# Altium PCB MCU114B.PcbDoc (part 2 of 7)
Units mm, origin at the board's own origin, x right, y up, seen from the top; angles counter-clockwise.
Board outline 105.51 x 58.76 mm, 8 copper layers (Top Layer, GND 2, Signal Layer 3, Power 4, Power 5, Signal Layer 6, GND 7, Bottom), stack 1.554 mm thick; 444 components, 418 nets, 1811 pads, 981 vias.
Unrouted connection lines stored in the file: 3.
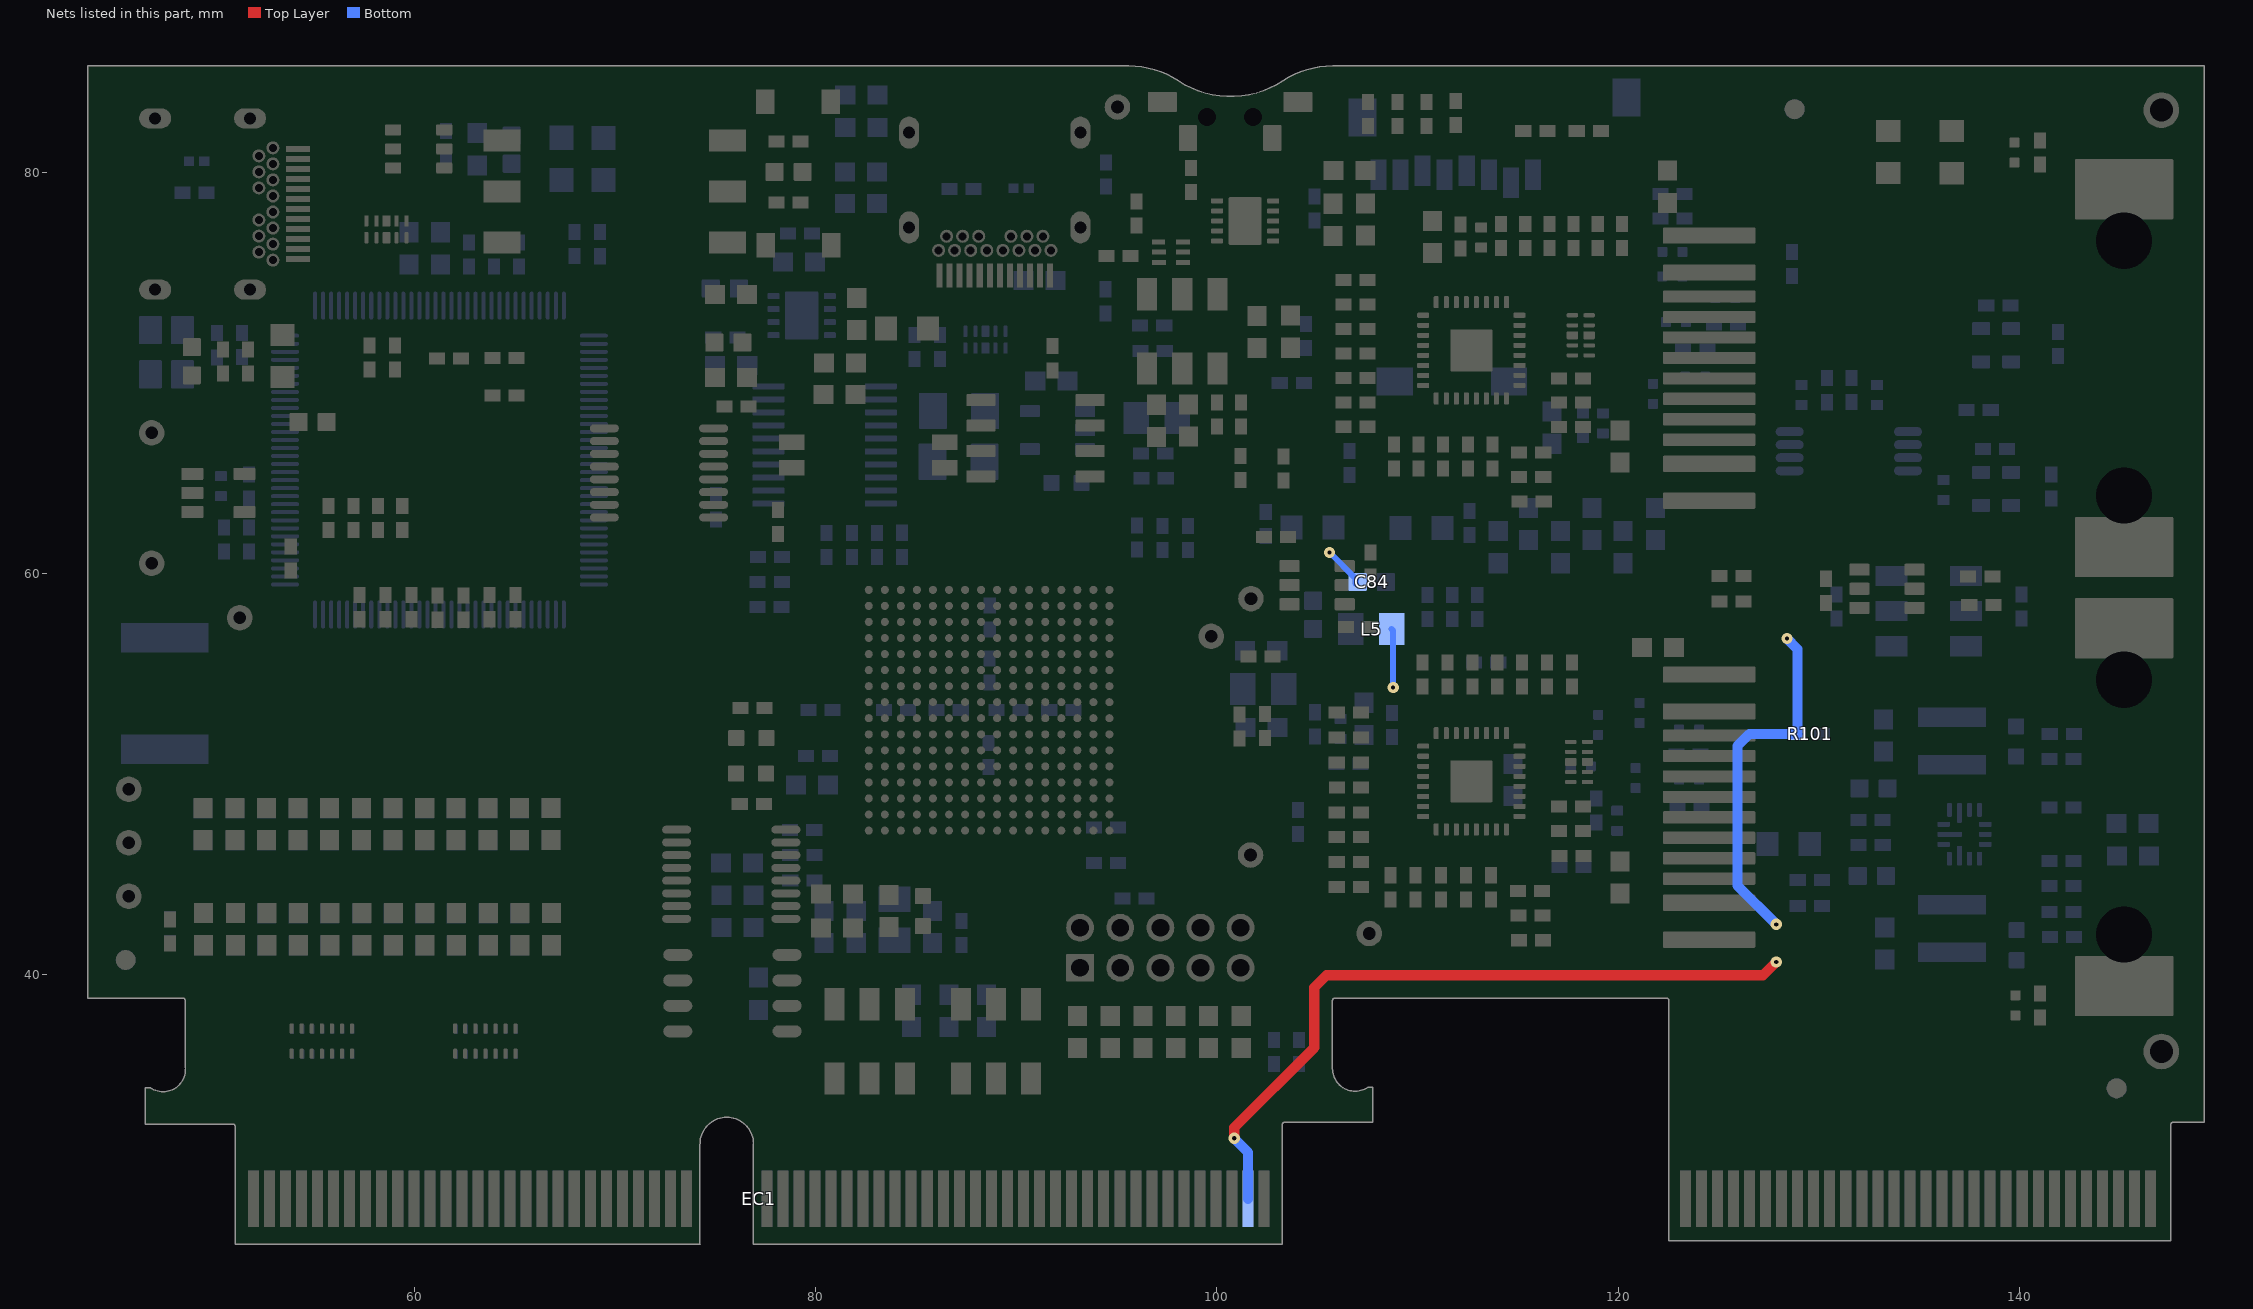
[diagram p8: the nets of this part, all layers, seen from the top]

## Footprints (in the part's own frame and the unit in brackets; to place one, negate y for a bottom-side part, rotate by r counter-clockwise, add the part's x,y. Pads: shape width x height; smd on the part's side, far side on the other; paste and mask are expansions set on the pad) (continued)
D0008A_N [mm] "SOIC, 8-Leads, Body 4.9x3.9mm, Pitch 1.27mm, IPC Medium Density"
  oval 1.45x0.6 smd: 1(-2.725,1.905) 2(-2.725,0.635) 3(-2.725,-0.635) 4(-2.725,-1.905) 5(2.725,-1.905) 6(2.725,-0.635) 7(2.725,0.635) 8(2.725,1.905)
  silkscreen extent -3.3,-2.5 0.9,2.5, body extent -3,-2.45 3,2.45, height 1.63
DBQ0016A_N [mm] "SOP, 16-Leads, Body 4.9x3.9mm, Pitch 0.635mm, IPC Medium Density"
  oval 1.45x0.4 smd: 1(-2.725,2.222) 2(-2.725,1.587) 3(-2.725,0.953) 4(-2.725,0.318) 5(-2.725,-0.318) 6(-2.725,-0.953) 7(-2.725,-1.587) 8(-2.725,-2.222) 9(2.725,-2.222) 10(2.725,-1.587) 11(2.725,-0.953) 12(2.725,-0.318) 13(2.725,0.318) 14(2.725,0.953) 15(2.725,1.587) 16(2.725,2.222)
  silkscreen extent -3.35,-2.5 1.1,2.68, body extent -3.01,-2.45 3.01,2.45, height 1.63
DBV0005A-MFG [mm]
  rrect17% 1.1x0.6 smd paste+0 mask+0: 1(-1.3,0.95) 2(-1.3,0) 3(-1.3,-0.95) 4(1.3,-0.95) 5(1.3,0.95)
  silkscreen extent -2.57,-1.53 0.87,1.53, body extent -1.95,-1.78 1.95,1.78, height 0.25
DBV0005A_N [mm] "SOT23, 5-Leads, Body 2.9x1.6mm, Pitch 0.95mm, Lead Span 2.8mm, IPC Medium Density"
  rrect17% 1x0.6 smd: 1(-1.375,0.95) 2(-1.375,0) 3(-1.375,-0.95) 4(1.375,-0.95) 5(1.375,0.95)
  silkscreen extent -0.25,-1.55 0.25,1.55, body extent -1.42,-1.46 1.42,1.46, height 1.09
DBV0006A_L [mm] "SOT23, 6-Leads, Body 2.9x1.6mm, Pitch 0.95mm, Lead Span 2.8mm, IPC High Density"
  rrect18% 0.8x0.55 smd: 1(-1.275,0.95) 2(-1.275,0) 3(-1.275,-0.95) 4(1.275,-0.95) 5(1.275,0) 6(1.275,0.95)
  silkscreen extent -1.55,-1.53 0.55,1.53, body extent -1.42,-1.46 1.42,1.46, height 1.12
DBV0006A_N [mm] "SOT23, 6-Leads, Body 2.9x1.6mm, Pitch 0.95mm, Lead Span 2.8mm, IPC Medium Density"
  rrect17% 1x0.6 smd: 1(-1.375,0.95) 2(-1.375,0) 3(-1.375,-0.95) 4(1.375,-0.95) 5(1.375,0) 6(1.375,0.95)
  silkscreen extent -1.68,-1.55 0.5,1.55, body extent -1.42,-1.46 1.42,1.46, height 1.12
DLF0004A-MFG [mm]
  rrect15% 0.9x0.65 smd paste-1000 mask+0: 1(-0.75,0.825) 2(-0.75,-0.825) 3(0.75,-0.825) 4(0.75,0.825)
  silkscreen extent -1.88,-0.13 1.05,0.95, body extent -1,-1.25 1,1.25, height 1
DQA0010A#1 [mm] "SON, 10-Leads, Body 1x2.5mm, Pitch 0.5mm, TI Recommended"
  rrect50% 0.565x0.2 smd: 1(-0.417,1) 2(-0.417,0.5) 4(-0.417,-0.5) 5(-0.417,-1) 6(0.417,-1) 7(0.417,-0.5) 9(0.417,0.5) 10(0.417,1)
  rrect28% 0.565x0.36 on Top Paste: 3(-0.417,0) 8(0.417,0)
  rrect25% 0.565x0.4 smd paste-0.2: 3(-0.417,0) 8(0.417,0)
  silkscreen extent -0.67,-1.45 0.55,1.45, body extent -0.55,-1.3 0.55,1.3, height 0.56
DQA0010A#2 [mm] "SON, 10-Leads, Body 1x2.5mm, Pitch 0.5mm, TI Recommended"
  rrect50% 0.565x0.2 smd: 1(-0.417,1) 2(-0.417,0.5) 4(-0.417,-0.5) 5(-0.417,-1) 6(0.417,-1) 7(0.417,-0.5) 9(0.417,0.5) 10(0.417,1)
  rrect28% 0.565x0.36 on Bottom Paste: 3(-0.417,0) 8(0.417,0)
  rrect25% 0.565x0.4 smd paste-0.2: 3(-0.417,0) 8(0.417,0)
  silkscreen extent -0.67,-1.45 0.55,1.45, body extent -0.55,-1.3 0.55,1.3, height 0.56
DRB0008B [mm] "SON, 8-Leads, Body 3x3mm, Pitch 0.65mm, Thermal Pad 2.4x1.65mm, TI Recommended"
  rrect33% 0.6x0.3 smd: 1(-1.4,0.975) 2(-1.4,0.325) 3(-1.4,-0.325) 4(-1.4,-0.975) 5(1.4,-0.975) 6(1.4,-0.325) 7(1.4,0.325) 8(1.4,0.975)
  rrect9% 1.47x1.06 on Bottom Paste: 9(0,-0.63) 9(0,0.63)
  rrect6% 1.65x2.4 smd paste-1.2 mask+0.05: 9(0,0)
  silkscreen extent -1.73,-1.73 1.73,1.73, body extent -1.5,-1.5 1.5,1.5, height 0.96
DRC0010R [mm] "VSON-10"
  rrect40% 0.6x0.25 smd: 1(-1.4,1) 2(-1.4,0.5) 3(-1.4,0) 4(-1.4,-0.5) 5(-1.4,-1) 6(1.4,-1) 7(1.4,-0.5) 8(1.4,0) 9(1.4,0.5) 10(1.4,1)
  rrect12% 1.65x2.4 smd paste-1 mask+0.05: 11(0,0)
  Top Layer region: -0.375,-1.65 -0.375,-1.2 -0.775,-1.2 -0.794,-1.196 -0.81,-1.185 -0.821,-1.169 -0.825,-1.15 -0.825,-1.15 -0.825,1.15 -0.821,1.169 -0.81,1.185 -0.794,1.196 -0.775,1.2 -0.775,1.2 -0.375,1.2 -0.375,1.65 -0.371,1.669 -0.36,1.685 -0.344,1.696 -0.325,1.7 -0.325,1.7 -0.325,1.7 -0.175,1.7 -0.175,1.7 -0.156,1.696 -0.14,1.685 -0.129,1.669 -0.125,1.65 -0.125,1.65 -0.125,1.2 0.125,1.2 0.125,1.65 0.129,1.669 0.14,1.685 0.156,1.696 0.175,1.7 0.175,1.7 0.175,1.7 0.325,1.7 0.325,1.7 0.344,1.696 0.36,1.685 0.371,1.669 0.375,1.65 0.375,1.65 0.375,1.2 0.775,1.2 0.794,1.196 0.81,1.185 0.821,1.169 0.825,1.15 0.825,1.15 0.825,-1.15 0.821,-1.169 0.81,-1.185 0.794,-1.196 0.775,-1.2 0.775,-1.2 0.375,-1.2 0.375,-1.65 0.371,-1.669 0.36,-1.685 0.344,-1.696 0.325,-1.7 0.325,-1.7 0.175,-1.7 0.156,-1.696 0.14,-1.685 0.129,-1.669 0.125,-1.65 0.125,-1.65 0.125,-1.2 -0.125,-1.2 -0.125,-1.65 -0.129,-1.669 -0.14,-1.685 -0.156,-1.696 -0.175,-1.7 -0.175,-1.7 -0.325,-1.7 -0.344,-1.696 -0.36,-1.685 -0.371,-1.669 -0.375,-1.65
  silkscreen extent -1.65,-1.65 1.65,1.65, body extent -1.5,-1.5 1.5,1.5, height 0.87
DSE0006A [mm] "TI recommended land pattern"
  rect 0.66x0.25 smd: 1(-0.62,0.5)
  rect 0.7x0.25 smd: 2(-0.6,0) 3(-0.6,-0.5) 4(0.6,-0.5) 5(0.6,0) 6(0.6,0.5)
  Top Layer region: -0.3,0.625 -0.25,0.625 -0.15,0.525 -0.15,0.375 -0.3,0.375
  silkscreen extent -0.9,-0.92 0.9,0.92, body extent -0.77,-0.77 0.77,0.77, height 0.8
EtherCAT_label [mm] "ETHERCAT_LABEL"
FCC_disclaimer [mm]
Fiducial10-20#1 [mm]
  round 1 smd mask+0.5: 1(0,0)
  Top Layer keep-out circle w1.178: c0,0 r0.5
Fiducial10-20#2 [mm]
  round 1 smd far side mask+0.5: 1(0,0)
  Top Layer keep-out circle w1.178: c0,0 r0.5
FP-830064296_SMT4_3MM4_2MM7-MFG [mm]
  rrect9% 1.4x1.15 smd paste+0 mask+0: 1(-1.1,-0.8) 2(1.1,-0.8) 3(1.1,0.8) 4(-1.1,0.8)
  silkscreen extent -2.17,-2.05 2.17,1.35, body extent -1.7,-1.35 1.7,1.35, height 0.8
FP-885012005053_0402-MFG [mm]
  rrect20% 0.5x0.5 smd paste+0 mask+0: 1(-0.5,0) 2(0.5,0)
  silkscreen extent -0.53,-0.63 0.53,0.63, body extent -0.5,-0.25 0.5,0.25, height 0.55
FP-885012006032_0603-MFG [mm]
  rrect13% 0.8x0.8 smd paste+0 mask+0: 1(-0.75,0) 2(0.75,0)
  silkscreen extent -0.85,-0.77 0.85,0.77, body extent -0.8,-0.4 0.8,0.4, height 0.87
FP-885012106012_0603-MFG [mm]
  rrect13% 0.8x0.8 smd paste+0 mask+0: 1(-0.75,0) 2(0.75,0)
  silkscreen extent -0.85,-0.77 0.85,0.77, body extent -0.8,-0.4 0.8,0.4, height 0.87
FP-885012205067_0402-MFG [mm]
  rrect20% 0.5x0.5 smd paste+0 mask+0: 1(-0.5,0) 2(0.5,0)
  silkscreen extent -0.53,-0.63 0.53,0.63, body extent -0.85,-0.38 0.85,0.38, height 0.25
FP-885012205086_0402-MFG [mm]
  rrect20% 0.5x0.5 smd paste+0 mask+0: 1(-0.5,0) 2(0.5,0)
  silkscreen extent -0.6,-0.63 0.6,0.63, body extent -0.5,-0.25 0.5,0.25, height 0.7
FP-CC0603KRX5R7BB106_0603-MFG [mm]
  rrect11% 0.9x0.9 smd paste+0 mask+0: 1(-0.7,0) 2(0.7,0)
  silkscreen extent -0.9,-0.82 0.9,0.82, body extent -1.35,-0.75 1.35,0.75, height 0.25
FP-CL388-IPC_C [mm]
  rect 0.515x0.472 smd paste+0 mask+0: 1(-0.379,0) 2(0.379,0)
  silkscreen extent -0.64,-0.67 0.64,0.67, body extent -0.5,-0.25 0.5,0.25, height 0.55
"FP-RMCF0402ZT0R00_0402 (1005 metric)-0" [mm]
  rrect20% 0.5x0.6 smd paste+0 mask+0: 1(-0.5,0) 2(0.5,0)
  body extent -0.5,-0.25 0.5,0.25, height 0.35
FP-RT0402FRE0751RL_0402-MFG [mm]
  rrect20% 0.5x0.6 smd paste+0 mask+0: 1(-0.5,0) 2(0.5,0)
  silkscreen extent -0.5,-0.71 0.5,0.7, body extent -0.5,-0.25 0.5,0.25, height 0.35
FP-TMM-105-01-T-D_HDR10-MFG [mm]
  rrect7% 1.39x1.39 hole 0.89 paste-2539.97 mask+0: 1(-4,-1)
  round 1.39 hole 0.89 paste-2539.97 mask+0: 2(-4,1) 3(-2,-1) 4(-2,1) 5(0,-1) 6(0,1) 7(2,-1) 8(2,1) 9(4,-1) 10(4,1)
  body extent -5.1,-2.13 5.1,2.13, height 0.25
LTST-C170TBKT_Blue [mm] "LITE-ON"
  rect 1.2x1.2 smd: 1(-1.05,0) 2(1.05,0)
  silkscreen extent -1.6,-1 2.2,1, body extent -1.05,-0.67 1.05,0.67, height 1.2
PDT0128A [mm] "Thin QFP, 128-Leads, Body 14x14mm, Pitch 0.4mm"
  oval 1.4x0.2 smd: 1(-7.7,6.2) 2(-7.7,5.8) 3(-7.7,5.4) 4(-7.7,5) 5(-7.7,4.6) 6(-7.7,4.2) 7(-7.7,3.8) 8(-7.7,3.4) 9(-7.7,3) 10(-7.7,2.6) 11(-7.7,2.2) 12(-7.7,1.8) 13(-7.7,1.4) 14(-7.7,1) 15(-7.7,0.6) 16(-7.7,0.2) 17(-7.7,-0.2) 18(-7.7,-0.6) 19(-7.7,-1) 20(-7.7,-1.4) 21(-7.7,-1.8) 22(-7.7,-2.2) 23(-7.7,-2.6) 24(-7.7,-3) 25(-7.7,-3.4) 26(-7.7,-3.8) 27(-7.7,-4.2) 28(-7.7,-4.6) 29(-7.7,-5) 30(-7.7,-5.4) 31(-7.7,-5.8) 32(-7.7,-6.2) 65(7.7,-6.2) 66(7.7,-5.8) 67(7.7,-5.4) 68(7.7,-5) 69(7.7,-4.6) 70(7.7,-4.2) 71(7.7,-3.8) 72(7.7,-3.4) 73(7.7,-3) 74(7.7,-2.6) 75(7.7,-2.2) 76(7.7,-1.8) 77(7.7,-1.4) 78(7.7,-1) 79(7.7,-0.6) 80(7.7,-0.2) 81(7.7,0.2) 82(7.7,0.6) 83(7.7,1) 84(7.7,1.4) 85(7.7,1.8) 86(7.7,2.2) 87(7.7,2.6) 88(7.7,3) 89(7.7,3.4) 90(7.7,3.8) 91(7.7,4.2) 92(7.7,4.6) 93(7.7,5) 94(7.7,5.4) 95(7.7,5.8) 96(7.7,6.2)
  oval 0.2x1.4 smd: 33(-6.2,-7.7) 34(-5.8,-7.7) 35(-5.4,-7.7) 36(-5,-7.7) 37(-4.6,-7.7) 38(-4.2,-7.7) 39(-3.8,-7.7) 40(-3.4,-7.7) 41(-3,-7.7) 42(-2.6,-7.7) 43(-2.2,-7.7) 44(-1.8,-7.7) 45(-1.4,-7.7) 46(-1,-7.7) 47(-0.6,-7.7) 48(-0.2,-7.7) 49(0.2,-7.7) 50(0.6,-7.7) 51(1,-7.7) 52(1.4,-7.7) 53(1.8,-7.7) 54(2.2,-7.7) 55(2.6,-7.7) 56(3,-7.7) 57(3.4,-7.7) 58(3.8,-7.7) 59(4.2,-7.7) 60(4.6,-7.7) 61(5,-7.7) 62(5.4,-7.7) 63(5.8,-7.7) 64(6.2,-7.7) 97(6.2,7.7) 98(5.8,7.7) 99(5.4,7.7) 100(5,7.7) 101(4.6,7.7) 102(4.2,7.7) 103(3.8,7.7) 104(3.4,7.7) 105(3,7.7) 106(2.6,7.7) 107(2.2,7.7) 108(1.8,7.7) 109(1.4,7.7) 110(1,7.7) 111(0.6,7.7) 112(0.2,7.7) 113(-0.2,7.7) 114(-0.6,7.7) 115(-1,7.7) 116(-1.4,7.7) 117(-1.8,7.7) 118(-2.2,7.7) 119(-2.6,7.7) 120(-3,7.7) 121(-3.4,7.7) 122(-3.8,7.7) 123(-4.2,7.7) 124(-4.6,7.7) 125(-5,7.7) 126(-5.4,7.7) 127(-5.8,7.7) 128(-6.2,7.7)
  silkscreen extent -7.7,-6.3 6.3,6.99, body extent -8,-8 8,8, height 1.07
PW0008A_N [mm] "TSOP, 8-Leads, Body 3x4.4mm, Pitch 0.65mm, IPC Medium Density"
  oval 1.4x0.45 smd: 1(-2.95,0.975) 2(-2.95,0.325) 3(-2.95,-0.325) 4(-2.95,-0.975) 5(2.95,-0.975) 6(2.95,-0.325) 7(2.95,0.325) 8(2.95,0.975)
  silkscreen extent -3.4,-1.55 1.85,1.55, body extent -3.21,-1.5 3.21,1.5, height 1.2
PW0020A-MFG [mm]
  rrect33% 1.6x0.3 smd paste-1000 mask+0: 1(-2.8,2.925) 2(-2.8,2.275) 3(-2.8,1.625) 4(-2.8,0.975) 5(-2.8,0.325) 6(-2.8,-0.325) 7(-2.8,-0.975) 8(-2.8,-1.625) 9(-2.8,-2.275) 10(-2.8,-2.925) 11(2.8,-2.925) 12(2.8,-2.275) 13(2.8,-1.625) 14(2.8,-0.975) 15(2.8,-0.325) 16(2.8,0.325) 17(2.8,0.975) 18(2.8,1.625) 19(2.8,2.275) 20(2.8,2.925)
  silkscreen extent -4.3,-3.3 1.63,3.3, body extent -3.2,-3.25 3.2,3.25, height 1.2
RHB0032M-MFG [mm]
  rrect40% 0.6x0.25 smd paste+0 mask+0: 1(-2.4,1.75) 2(-2.4,1.25) 3(-2.4,0.75) 4(-2.4,0.25) 5(-2.4,-0.25) 6(-2.4,-0.75) 7(-2.4,-1.25) 8(-2.4,-1.75) 17(2.4,-1.75) 18(2.4,-1.25) 19(2.4,-0.75) 20(2.4,-0.25) 21(2.4,0.25) 22(2.4,0.75) 23(2.4,1.25) 24(2.4,1.75)
  rrect40% 0.25x0.6 smd paste+0 mask+0: 9(-1.75,-2.4) 10(-1.25,-2.4) 11(-0.75,-2.4) 12(-0.25,-2.4) 13(0.25,-2.4) 14(0.75,-2.4) 15(1.25,-2.4) 16(1.75,-2.4) 25(1.75,2.4) 26(1.25,2.4) 27(0.75,2.4) 28(0.25,2.4) 29(-0.25,2.4) 30(-0.75,2.4) 31(-1.25,2.4) 32(-1.75,2.4)
  rrect5% 2.1x2.1 smd paste-1000 mask+0: 33(0,0)
  silkscreen extent -3.4,-2.55 2.55,2.55, body extent -2.8,-2.8 2.8,2.8, height 0.25
RQR0014A-MFG [mm]
  rrect40% 0.625x0.25 smd paste+0 mask+0: 1(-1.038,0.5) 2(-1.038,0) 3(-1.038,-0.5) 8(1.038,-0.5) 10(1.038,0.5)
  rrect40% 0.25x0.675 smd paste+0 mask+0: 4(-0.75,-1.212) 5(-0.25,-1.212) 7(0.75,-1.212) 11(0.75,1.212) 13(-0.25,1.212) 14(-0.75,1.212)
  rrect40% 0.25x0.975 smd paste+0 mask+0: 6(0.25,-1.062) 12(0.25,1.062)
  rrect40% 1.225x0.25 smd paste+0 mask+0: 9(0.737,0)
  silkscreen extent -2.02,-1.55 1.35,1.55, body extent -1.15,-1.35 1.15,1.35, height 1
RVZ0014A [mm] "SON, 14-Leads, Body 3.5x1.35mm, Pitch 0.5mm"
  rrect50% 0.5x0.2 smd: 1(-0.625,1.5) 2(-0.625,1) 3(-0.625,0.5) 4(-0.625,0) 5(-0.625,-0.5) 6(-0.625,-1) 7(-0.625,-1.5) 8(0.625,-1.5) 9(0.625,-1) 10(0.625,-0.5) 11(0.625,0) 12(0.625,0.5) 13(0.625,1) 14(0.625,1.5)
  silkscreen extent -1.18,-2.05 1.18,2.05, body extent -0.72,-1.8 0.72,1.8, height 0.55
SOD-123 [mm] "On Semi recommended land pattern"
  rect 0.915x1.22 smd: 1(-1.637,0) 2(1.637,0)
  silkscreen extent -2.74,-1.17 2.03,1.17, body extent -1.93,-0.9 1.93,0.9, height 1.35
SOIC-8 [mm] "duplicate of SO-8.  SOIC, 8-Leads, Body 5.0x4.0mm (max), Pitch 1.27mm, IPC Medium Density"
  rrect17% 1.45x0.6 smd: 1(-2.725,1.905) 2(-2.725,0.635) 3(-2.725,-0.635) 4(-2.725,-1.905) 5(2.725,-1.905) 6(2.725,-0.635) 7(2.725,0.635) 8(2.725,1.905)
  silkscreen extent -3.5,-2.5 0.9,2.5, body extent -3,-2.45 3,2.45, height 1.63
SW_218-2LP [mm] "SMD, 4-Leads, Body 3.71x5.8mm, Pitch 1.27mm"
  rect 1.27x0.76 smd: 1(-3.81,0.635) 2(-3.81,-0.635) 3(3.81,-0.635) 4(3.81,0.635)
  silkscreen extent -2.9,-1.86 2.9,2.09, body extent -4.22,-1.86 4.22,1.85, height 2.62
SW_1188E [mm] "SMD, 4-Leads, Body 7.8x3.5mm"
  rrect10% 1x1.45 smd: 1(-1.1,3.375) 2(-1.1,-3.375)
  rrect11% 1.3x0.9 smd: 3(0.7,2.1) 4(0.7,-2.1)
  round 0 hole 0.9 unplated: ""(-0.35,1.15) ""(-0.35,-1.15)
  silkscreen extent -1.97,-2.28 0.95,2.28, body extent -2.55,-3.9 1.05,3.9, height 3.5
SW_CAS-D20TA [mm] "SMD, 6-Leads, Body 5.4x3.9mm, Pitch 1.75mm"
  rect 1.6x1 smd: 1(-1.85,1.75) 2(-1.85,0) 3(-1.85,-1.75) 4(1.85,1.75) 5(1.85,0) 6(1.85,-1.75)
  silkscreen extent -1.95,-2.7 1.95,2.9, body extent -2.1,-2.7 2.1,2.7, height 2.5
TI_Stacked_Overlay_Small [mm]
  silkscreen extent -10.63,-2.49 10.63,2.49
TP_50MIL-25MILHOLE [mm]
  round 1.27 hole 0.635: 1(0,0)
WEEE_Minimum [mm] "WEEElie bin"
  silkscreen extent -2.42,-4.38 2.52,2.65
WL-SMCW_Green_0805 [mm] "SMD, 2-Leads, Body 2x1.25mm"
  rect 1.1x1.2 smd: 1(-1.05,0) 2(1.05,0)
  silkscreen extent -2.4,-1.1 1.5,1.1, body extent -1,-0.62 1,0.63, height 0.7
WL-SMCW_RED_0805 [mm] "SMD, 2-Leads, Body 1.6x0.8mm"
  rect 1.1x1.2 smd: 1(-1.05,0) 2(1.05,0)
  silkscreen extent -2.4,-1.1 1.5,1.1, body extent -1,-0.62 1,0.63, height 0.7
Wurth_632_723_300_011 [mm] "Connector, Receptacle, USB Type C, R/A"
  rect 0.3x1.2 smd: A1(-2.75,10.58) A2(-2.25,10.58) A3(-1.75,10.58) A4(-1.25,10.58) A5(-0.75,10.58) A6(-0.25,10.58) A7(0.25,10.58) A8(0.75,10.58) A9(1.25,10.58) A10(1.75,10.58) A11(2.25,10.58) A12(2.75,10.58)
  round 0.65 hole 0.4 mask+0: B1(2.8,9.32) B2(2.4,8.62) B3(1.6,8.62) B4(1.2,9.32) B5(0.8,8.62) B6(0.4,9.32) B7(-0.4,9.32) B8(-0.8,8.62) B9(-1.2,9.32) B10(-1.6,8.62) B11(-2.4,8.62) B12(-2.8,9.32) M1(2,9.32) M2(-2,9.32)
  rrect100% 1x1.6 hole 0.6 slot 1.2 at 90 deg: S1(-4.27,8.18) S2(-4.27,3.45) S3(4.27,3.45) S4(4.27,8.18)
  silkscreen extent -4.37,0.15 4.37,10.36, body extent -4.37,-0.96 4.37,10.83, height 3.07
Wurth_750315371 [mm] "SMD, Body 12.6x8.3mm, Pitch 2.54mm"
  rect 1.83x1.09 smd: 1(-5.62,2.54) 2(-5.62,0) 3(-5.62,-2.54) 4(5.62,-2.54) 5(5.62,0) 6(5.62,2.54)
  silkscreen extent -6.3,-4.15 6.3,4.4, body extent -6.35,-4.2 6.35,4.2, height 4.11
Wurth_7498010210A [mm] "Connector, RJ45, 1x1, Gold, R/A, SMT"
  rrect12% 4.6x0.81 smd: 1(-20.69,6.61) 2(-20.69,4.77) 11(-20.69,-4.77) 12(-20.69,-6.61)
  rrect16% 4.6x0.61 smd: 3(-20.69,3.57) 4(-20.69,2.55) 5(-20.69,1.53) 6(-20.69,0.51) 7(-20.69,-0.51) 8(-20.69,-1.53) 9(-20.69,-2.55) 10(-20.69,-3.57)
  rrect3% 4.9x3 smd: 13(0,8.92) 14(0,-8.92)
  round 2.5 hole 2.8 unplated mask+0.102: ALIGN1(0,6.35) ALIGN2(0,-6.35)
  body extent -21.42,-9.65 5.43,9.65, height 15.22
XFL4015 [mm] "SMD, 2-Leads, Body 4x4mm"
  rect 0.98x3.4 smd: 1(-1.185,0) 2(1.185,0)
  silkscreen extent -2.15,-2.15 2.15,2.15, body extent -2.15,-2.15 2.15,2.15, height 1.6
ZEJ0256A-MFG [mm]
  round 0.4 smd paste+0 mask-1000: A1(-6,6) A2(-5.2,6) A3(-4.4,6) A4(-3.6,6) A5(-2.8,6) A6(-2,6) A7(-1.2,6) A8(-0.4,6) A9(0.4,6) A10(1.2,6) A11(2,6) A12(2.8,6) A13(3.6,6) A14(4.4,6) A15(5.2,6) A16(6,6) B1(-6,5.2) B2(-5.2,5.2) B3(-4.4,5.2) B4(-3.6,5.2) B5(-2.8,5.2) B6(-2,5.2) B7(-1.2,5.2) B8(-0.4,5.2) B9(0.4,5.2) B10(1.2,5.2) B11(2,5.2) B12(2.8,5.2) B13(3.6,5.2) B14(4.4,5.2) B15(5.2,5.2) B16(6,5.2) C1(-6,4.4) C2(-5.2,4.4) C3(-4.4,4.4) C4(-3.6,4.4) C5(-2.8,4.4) C6(-2,4.4) C7(-1.2,4.4) C8(-0.4,4.4) C9(0.4,4.4) C10(1.2,4.4) C11(2,4.4) C12(2.8,4.4) C13(3.6,4.4) C14(4.4,4.4) C15(5.2,4.4) C16(6,4.4) D1(-6,3.6) D2(-5.2,3.6) D3(-4.4,3.6) D4(-3.6,3.6) D5(-2.8,3.6) D6(-2,3.6) D7(-1.2,3.6) D8(-0.4,3.6) D9(0.4,3.6) D10(1.2,3.6) D11(2,3.6) D12(2.8,3.6) D13(3.6,3.6) D14(4.4,3.6) D15(5.2,3.6) D16(6,3.6) E1(-6,2.8) E2(-5.2,2.8) E3(-4.4,2.8) E4(-3.6,2.8) E5(-2.8,2.8) E6(-2,2.8) E7(-1.2,2.8) E8(-0.4,2.8) E9(0.4,2.8) E10(1.2,2.8) E11(2,2.8) E12(2.8,2.8) E13(3.6,2.8) E14(4.4,2.8) E15(5.2,2.8) E16(6,2.8) F1(-6,2) F2(-5.2,2) F3(-4.4,2) F4(-3.6,2) F5(-2.8,2) F6(-2,2) F7(-1.2,2) F8(-0.4,2) F9(0.4,2) F10(1.2,2) F11(2,2) F12(2.8,2) F13(3.6,2) F14(4.4,2) F15(5.2,2) F16(6,2) G1(-6,1.2) G2(-5.2,1.2) G3(-4.4,1.2) G4(-3.6,1.2) G5(-2.8,1.2) G6(-2,1.2) G7(-1.2,1.2) G8(-0.4,1.2) G9(0.4,1.2) G10(1.2,1.2) G11(2,1.2) G12(2.8,1.2) G13(3.6,1.2) G14(4.4,1.2) G15(5.2,1.2) G16(6,1.2) H1(-6,0.4) H2(-5.2,0.4) H3(-4.4,0.4) H4(-3.6,0.4) H5(-2.8,0.4) H6(-2,0.4) H7(-1.2,0.4) H8(-0.4,0.4) H9(0.4,0.4) H10(1.2,0.4) H11(2,0.4) H12(2.8,0.4) H13(3.6,0.4) H14(4.4,0.4) H15(5.2,0.4) H16(6,0.4) J1(-6,-0.4) J2(-5.2,-0.4) J3(-4.4,-0.4) J4(-3.6,-0.4) J5(-2.8,-0.4) J6(-2,-0.4) J7(-1.2,-0.4) J8(-0.4,-0.4) J9(0.4,-0.4) J10(1.2,-0.4) J11(2,-0.4) J12(2.8,-0.4) J13(3.6,-0.4) J14(4.4,-0.4) J15(5.2,-0.4) J16(6,-0.4) K1(-6,-1.2) K2(-5.2,-1.2) K3(-4.4,-1.2) K4(-3.6,-1.2) K5(-2.8,-1.2) K6(-2,-1.2) K7(-1.2,-1.2) K8(-0.4,-1.2) K9(0.4,-1.2) K10(1.2,-1.2) K11(2,-1.2) K12(2.8,-1.2) K13(3.6,-1.2) K14(4.4,-1.2) K15(5.2,-1.2) K16(6,-1.2) L1(-6,-2) L2(-5.2,-2) L3(-4.4,-2) L4(-3.6,-2) L5(-2.8,-2) L6(-2,-2) L7(-1.2,-2) L8(-0.4,-2) L9(0.4,-2) L10(1.2,-2) L11(2,-2) L12(2.8,-2) L13(3.6,-2) L14(4.4,-2) L15(5.2,-2) L16(6,-2) M1(-6,-2.8) M2(-5.2,-2.8) M3(-4.4,-2.8) M4(-3.6,-2.8) M5(-2.8,-2.8) M6(-2,-2.8) M7(-1.2,-2.8) M8(-0.4,-2.8) M9(0.4,-2.8) M10(1.2,-2.8) M11(2,-2.8) M12(2.8,-2.8) M13(3.6,-2.8) M14(4.4,-2.8) M15(5.2,-2.8) M16(6,-2.8) N1(-6,-3.6) N2(-5.2,-3.6) N3(-4.4,-3.6) N4(-3.6,-3.6) N5(-2.8,-3.6) N6(-2,-3.6) N7(-1.2,-3.6) N8(-0.4,-3.6) N9(0.4,-3.6) N10(1.2,-3.6) N11(2,-3.6) N12(2.8,-3.6) N13(3.6,-3.6) N14(4.4,-3.6) N15(5.2,-3.6) N16(6,-3.6) P1(-6,-4.4) P2(-5.2,-4.4) P3(-4.4,-4.4) P4(-3.6,-4.4) P5(-2.8,-4.4) P6(-2,-4.4) P7(-1.2,-4.4) P8(-0.4,-4.4) P9(0.4,-4.4) P10(1.2,-4.4) P11(2,-4.4) P12(2.8,-4.4) P13(3.6,-4.4) P14(4.4,-4.4) P15(5.2,-4.4) P16(6,-4.4) R1(-6,-5.2) R2(-5.2,-5.2) R3(-4.4,-5.2) R4(-3.6,-5.2) R5(-2.8,-5.2) R6(-2,-5.2) R7(-1.2,-5.2) R8(-0.4,-5.2) R9(0.4,-5.2) R10(1.2,-5.2) R11(2,-5.2) R12(2.8,-5.2) R13(3.6,-5.2) R14(4.4,-5.2) R15(5.2,-5.2) R16(6,-5.2) T1(-6,-6) T2(-5.2,-6) T3(-4.4,-6) T4(-3.6,-6) T5(-2.8,-6) T6(-2,-6) T7(-1.2,-6) T8(-0.4,-6) T9(0.4,-6) T10(1.2,-6) T11(2,-6) T12(2.8,-6) T13(3.6,-6) T14(4.4,-6) T15(5.2,-6) T16(6,-6)
  silkscreen extent -7.25,-6.65 6.65,6.65, body extent -7.05,-7.05 7.05,7.05, height 0.25

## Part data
B1: library part CMP-0860874-2, "3.3-V and 2.5-V LVCMOS High-Performance Clock Buffer Family, PW0008A (TSSOP-8)", Alternate Manufacturer="Texas Instruments", Alternate PartNumber=LMK1C1104PWR
C1 C2 C3 C4 C9 C19: library part CMP-0006227-2, "CAP, CERM, 0.01 uF, 16 V, +/- 10%, X7R, 0402", Cap_Case=0402, Manufacturer="Wurth Elektronik", Supplier Part Number 1=710-885012205031, TempCo=X7R, Tolerance_%=10%, Value1=Unknown, Value2=16V, ValueDisplayed=0.01uF
C5 C6 C11 C15 C16 C22 C23 C25 C27 C29 C30 C31 C35 C36 C37 C38 C39 C40 C41 C42 C43 C51 C52 C55 C56 C57 C58 C59 C60 C61 C68 C69 C70 C71 C72 C73 C74 C75 C76 C77 C78 C79 C80 C81 C82 C83 C86 C90 C98 C100 C103 C106 C114 C116 C126 C152 C153: library part CMP-0006228-2, "CAP, CERM, 0.1 uF, 16 V, +/- 10%, X7R, 0402", Cap_Case=0402, Manufacturer="Wurth Elektronik", Supplier Part Number 1=732-7532-1-ND, TempCo=X7R, Tolerance_%=10%, Value1=Unknown, Value2=16V, ValueDisplayed=0.1uF
C7 C8 C12: library part CMP-0064924-2, "CAP, CERM, 1 uF, 10 V,+/- 20%, X5R, 0402", Cap_Case=0402, Manufacturer="Wurth Elektronik", Supplier Part Number 1=732-7489-1-ND, TempCo=X5R, Tolerance_%=20%, Value1=Unknown, Value2=10V, ValueDisplayed=1uF
C10: library part CMP-0006222-2, "CAP, CERM, 2.2 uF, 10 V, +/- 20%, X5R, 0402", Cap_Case=0402, Manufacturer="Wurth Elektronik", Supplier Part Number 1=710-885012105013, TempCo=X5R, Tolerance_%=20%, Value1=Unknown, Value2=10V, ValueDisplayed=2.2uF
C13 C14: library part CMP-0006345-2, "CAP, CERM, 12 pF, 50 V, +/- 5%, C0G/NP0, 0402", Cap_Case=0402, Manufacturer="Samsung Electro-Mechanics", Supplier Part Number 1=1276-1178-1-ND, TempCo=C0G/NP0, Tolerance_%=5%, Value1=Unknown, Value2=50V, ValueDisplayed=12pF
C17 C18 C21 C24 C26 C28 C53 C54 C84 C85: library part CMP-0001560-1, "Multilayer Ceramic Capacitors 10uF 16V X5R 10% SMD 0603 85°C Paper T/R - Tape an", Digikey Part Number=311-3486-1-ND, Manufacturer=Yageo, Mouser Part Number=603-CC0603KRX57BB106, Operating Temperature Range="-55°C to +85°C", TempCo=15%, Temperature Characteristic=X5R, Tolerance_%=10%, ValueDisplayed=10uF
C20 C44: library part CMP-13271-000627-1, "Cap Ceramic 3.3nF 50V X7R ±10% SMD 0402 +125°C Paper T/R", Capacitance=3.3nF, Case Code (Imperial)=0402, Case Code (Metric)=1005, Dielectric=X7R, Max Operating Temperature=125°C, Min Operating Temperature=-55°C, Package Quantity=1, Tolerance=10%, Voltage=50V
C32 C33 C64 C65 C66 C67 C120: library part CMP-0006825-5, "CAP, CERM, 2.2 uF, 16 V, +/- 20%, X5R, 0603", Cap_Case=0603, Manufacturer="Wurth Elektronik", Supplier Part Number 1=732-7915-1-ND, TempCo=X5R, Tolerance_%=20%, Value1=Unknown, Value2=16V, ValueDisplayed=2.2uF
C34: library part CMP-0082066-1, "CAP, CERM, 10 pF, 3000 V,+/- 5%, C0G/NP0, AEC-Q200 Grade 1, 1812", Cap_Case=1812, Manufacturer=Kemet, Supplier Part Number 1=399-7113-1-ND, TempCo=C0G/NP0, Tolerance_%=5%, Value2=3000V, ValueDisplayed=10pF
C45 C63 C118 C119: library part CMP-0097305-1, "4.7 µF ±20% 10V Ceramic Capacitor X5R 0603 (1608 Metric)", Digikey Part Number=732-7909-1-ND, Manufacturer="Wurth Electronics", Mouser Part Number=710-885012106012, Operating Temperature Range="-55°C to +85°C", TempCo=15%, Temperature Characteristic=X5R, Tolerance_%=20%, ValueDisplayed=4.7uF
C46: library part CMP-0011440-2, "CAP, TA, 0.1 uF, 35 V, +/- 10%, 20 ohm, SMD", Cap_Case=A, Manufacturer=Vishay-Sprague, Supplier Part Number 1=718-1109-1-ND, Tolerance_%=10%, Value1="20 ohm", Value2=35V, ValueDisplayed=0.1uF
C47: library part CMP-0081926-1, "CAP, TA, 68 µF, 10 V, +/- 20%, 1.5 ohm, SMD", Cap_Case=3216-18, Manufacturer=AVX, Supplier Part Number 1=478-4925-1-ND, Tolerance_%=20%, Value1="1.5 ohm", Value2=10V, ValueDisplayed=68µF
C48 C50: library part CMP-0096972-1, "10 pF ±5% 25V Ceramic Capacitor C0G, NP0 0603 (1608 Metric)", Digikey Part Number=732-7774-1-ND, Manufacturer="Wurth Electronics", Mouser Part Number=710-885012006032, Operating Temperature Range="-55°C to +125°C", TempCo=30ppm/°C, Temperature Characteristic=NP0, Tolerance_%=5%, ValueDisplayed=10pF
C49 C97 C113 C125: library part CMP-0007324-5, "CAP, CERM, 22 uF, 10 V, +/- 20%, X5R, 0603", Cap_Case=0603, Manufacturer=MuRata, Supplier Part Number 1=490-10476-1-ND, TempCo=X5R, Tolerance_%=20%, Value1=Unknown, Value2=10V, ValueDisplayed=22uF
C62 C124: library part CMP-0006829-4, "CAP, CERM, 0.1 uF, 16 V, +/- 10%, X7R, 0603", Cap_Case=0603, Manufacturer="Wurth Elektronik", Supplier Part Number 1=710-885012206046, TempCo=X7R, Tolerance_%=10%, Value1=Unknown, Value2=16V, ValueDisplayed=0.1uF
C87 C95 C102 C111: library part CMP-0096737-1, "100 nF ±10% 50V Ceramic Capacitor X7R 0402 (1005 Metric)", Manufacturer=Wurth, Operating Temperature Range="-55°C to +125°C", TempCo=15%, Temperature Characteristic=X7R, Tolerance_%=10%, ValueDisplayed=100nF
C88 C96 C104 C112: library part CMP-0086061-1, "CAP, CERM, 1 µF, 25 V,+/- 10%, X5R, 0402", Cap_Case=0402, Manufacturer=MuRata, TempCo=X5R, Tolerance_%=10%, Value2=25V, ValueDisplayed=1µF
C89 C105: library part CMP-0006283-2, "CAP, CERM, 2.2 uF, 35 V, +/- 10%, X5R, 0402", Cap_Case=0402_065, Manufacturer=TDK, Supplier Part Number 1=445-9028-1-ND, TempCo=X5R, Tolerance_%=10%, Value1="0.005925 ohm", Value2=35V, ValueDisplayed=2.2uF
C91 C92 C93 C94 C107 C108 C109 C110: library part CMP-0096999-1, "4.7 pF ±0.5pF 50V Ceramic Capacitor C0G, NP0 0402 (1005 Metric)", Digikey Part Number=732-7467-1-ND, Manufacturer="Wurth Electronics", Mouser Part Number=710-885012005053, Operating Temperature Range="-55°C to +125°C", TempCo=30ppm/°C, Temperature Characteristic=NP0, ValueDisplayed=4.7pF
C99 C115: library part CMP-0007313-5, "CAP, CERM, 47 uF, 6.3 V, +/- 20%, X5R, 0603", Cap_Case=0603, Manufacturer=MuRata, TempCo=X5R, Tolerance_%=20%, Value1=Unknown, Value2=6.3V, ValueDisplayed=47uF
C101 C117: library part CMP-0090364-1, "10000pF ±10% 50V Ceramic Capacitor X7R 0402 (1005 Metric)", Digikey Part Number=732-7562-1-ND, Manufacturer="Wurth Electronics", Mouser Part Number=710-885012205067, Operating Temperature Range="-55°C to +125°C", TempCo=15%, Temperature Characteristic=X7R, Tolerance_%=10%, ValueDisplayed=10000pF
C121 C122 C123: library part CMP-0006831-4, "CAP, CERM, 1 uF, 16 V, +/- 10%, X7R, 0603", Cap_Case=0603, Manufacturer="Wurth Elektronik", Supplier Part Number 1=710-885012206052, TempCo=X7R, Tolerance_%=10%, Value1=Unknown, Value2=16V, ValueDisplayed=1uF
C128 C129 C130 C131 C132 C133 C134 C135 C136 C137 C138 C139 C140 C141 C142 C143 C144 C145 C146 C147 C148 C149 C150 C151: library part CMP-0006920-4, "CAP, CERM, 330 pF, 50 V, +/- 5%, C0G/NP0, 0603", Cap_Case=0603, Manufacturer=Kemet, Supplier Part Number 1=399-1068-1-ND, TempCo=C0G/NP0, Tolerance_%=5%, Value1=Unknown, Value2=50V, ValueDisplayed=330pF
D1 D7 D9: library part CMP-0002960-2, "LED, Bright Green, SMD", Color="Bright Green", Manufacturer="Wurth Elektronik", Power_TotalModule=72mW, Supplier Part Number 1=732-4986-1-ND, Value1=0.072W, Value2=2V
D1:A D2:A: library part CMP-0028360-2, "Diode, Schottky, 40 V, 1 A, SOD-123", Manufacturer="Diodes Inc.", Value1=1A, Value2=0.45V
D2 D3 D4 D8: library part CMP-0002951-3, "LED, Red, SMD", Color=Red, Manufacturer="Wurth Elektronik", Power_TotalModule=72mW, Value1=0.072W, Value2=1.9V
D5 D6: library part CMP-0002889-2, "LED, Blue, SMD", Color=Blue, Manufacturer=Lite-On, Value1=W, Value2=3.3V
EC1: library part CMP-0003813-3, "C2000 controlCARD-120HSEC Edge Connector for Samtec HSEC8-160-01-L-DV-A-BL", Manufacturer=Any
EC2: library part CMP-0081961-1, "C2000 controlCARD-180HSEC (60-pin addon) Edge connector for Samtec HSEC8-130-01-L-DV-A", Manufacturer=Any
FID1 FID2 FID3 FID4 FID5 FID6: library part CMP-0077181-1, "Fiducial mark.  There is nothing to buy or mount.", Manufacturer=N/A
J1 J4: library part CMP-0080891-1, "Connector, Receptacle, USB Type C, R/A", Color=Black, Current_A=3A, Manufacturer="Wurth Elektronik", Supplier Part Number 1=732-9618-1-ND, Voltage_V=5V
J2: library part CMP-0075148-2, "Connector, Micro SD, R/A, SMD", Manufacturer=3M, Supplier Part Number 1=3M5607CT-ND
J3: library part CMP-0086568-1, "Board-To-Board Connector, TMM Series, 10 Contacts, Header, 2 mm, Through Hole, 2 Rows", Current_A=3.2A, Manufacturer=Samtec, Voltage_V=281V
J5 J6: library part CMP-0086350-1, "Connector, RJ45, 1x1, Gold, R/A, SMT", Manufacturer="Wurth Elektronik"
L1 L2: library part CMP-0061147-1, "Inductor, Shielded, Composite, 470 nH, 3.5 A, 0.0076 ohm, SMD", Manufacturer=Coilcraft, Supplier Part Number 1=994-XFL4015-471MEC, Value1="0.0076 ohm", Value2=3.5A, ValueDisplayed=470nH
L3 L4: library part CMP-0003093-1, "Ferrite Bead, 60 ohm @ 100 MHz, 3 A, 0805", Manufacturer="Wurth Elektronik", PartNumber=742792063, Supplier Part Number 1=732-1612-1-ND, Value1="0.025 ohm", Value2=3A
L5: library part CMP-0003073-1, "Ferrite Bead, 220 ohm @ 100 MHz, 2 A, 0805", Manufacturer="Wurth Elektronik", PartNumber=742792022, Supplier Part Number 1=732-1614-1-ND, Value1="0.05 ohm", Value2=2A
Logo1: library part CMP-0074844-1
Logo2: library part CMP-0074838-1, "Texas Instrument Corporate Signature"
Logo3: library part CMP-0074847-1, "FCC_disclaimer"
Logo4: library part CMP-0074769-3, Manufacturer="Texas Instruments"
Logo5: library part CMP-0084011-3, "EtherCAT logo"
R1 R10 R11 R31 R36 R37 R38 R43 R51 R54 R72 R100 R103: library part CMP-0077731-1, "RES, 10.0 k, 1%, 0.063 W, AEC-Q200 Grade 0, 0402", Manufacturer="Yageo America", Power_W=63mW, Supplier Part Number 1=YAG3436CT-ND, TempCo="100 ppm/C", Tolerance_%=1%, Value2=0.063W, Value_Code=10k0, ValueDisplayed=10.0k
R2 R46 R58 R73 R80 R81 R82 R83 R84 R86 R87 R91 R92 R93 R97 R99 R101 R110 R144 R203: library part CMP-0026992-3, "RES, 0, 5%, 0.1 W, AEC-Q200 Grade 0, 0402", Manufacturer=Panasonic, Power_W=100mW, Supplier Part Number 1=P0.0JCT-ND, TempCo="600 ppm/C", Tolerance_%=5%, Value2=0.1W, Value_Code=0000, ValueDisplayed=0
R3 R4 R5 R6: library part CMP-0026852-3, "RES, 1.0 k, 5%, 0.063 W, AEC-Q200 Grade 0, 0402", Manufacturer=Vishay-Dale, Power_W=63mW, Supplier Part Number 1=541-1.0KJCT-ND, TempCo="200 ppm/C", Tolerance_%=5%, Value2=0.063W, Value_Code=1k00, ValueDisplayed=1.0k
R7: library part CMP-0026824-3, "RES, 100, 5%, 0.063 W, AEC-Q200 Grade 0, 0402", Manufacturer=Vishay-Dale, Power_W=63mW, Supplier Part Number 1=541-100JCT-ND, TempCo="200 ppm/C", Tolerance_%=5%, Value2=0.063W, Value_Code=100R, ValueDisplayed=100
R8 R9: library part CMP-0026699-1, "RES, 470, 1%, 0.1 W, AEC-Q200 Grade 0, 0402", Manufacturer=Panasonic, Power_W=100mW, Supplier Part Number 1=P470LCT-ND, TempCo="100 ppm/C", Tolerance_%=1%, Value2=0.1W, Value_Code=470R, ValueDisplayed=470
R12: library part CMP-0026413-2, "RES, 4.87 k, 1%, 0.063 W, AEC-Q200 Grade 0, 0402", Manufacturer=Vishay-Dale, Power_W=63mW, Supplier Part Number 1=541-4.87KLCT-ND, TempCo="100 ppm/C", Tolerance_%=1%, Value2=0.063W, Value_Code=4k87, ValueDisplayed=4.87k
R13: library part CMP-0092664-1, "51 Ohms ±1% 0.063W, 1/16W Chip Resistor 0402 (1005 Metric) - Thin Film", Digikey Part Number=13-RT0402FRE0751RLCT-ND, Manufacturer=Yageo, Mouser Part Number=603-RT0402FRE0751RL, Operating Temperature Range="-55°C to +155°C", Part Number=RT0402FRE0751RL, Power_W=63mW, TempCo=50ppm/°C, Tolerance_%=1%
R14 R34 R35 R94 R138: library part CMP-0026962-3, "RES, 680, 5%, 0.063 W, AEC-Q200 Grade 0, 0402", Manufacturer=Vishay-Dale, Power_W=63mW, Supplier Part Number 1=541-680JCT-ND, TempCo="200 ppm/C", Tolerance_%=5%, Value2=0.063W, Value_Code=680R, ValueDisplayed=680
R15 R77 R136 R170: library part CMP-0026757-1, "RES, 1.00 M, 1%, 0.063 W, AEC-Q200 Grade 0, 0402", Manufacturer="Stackpole Electronics Inc", Power_W=63mW, Supplier Part Number 1=RMCF0402FT1M00CT-ND, TempCo="100 ppm/C", Tolerance_%=1%, Value2=0.063W, Value_Code=1M00, ValueDisplayed=1.00M
R16 R17 R79: library part CMP-0025932-5, "RES, 5.1 k, 5%, 0.1 W, 0603", Manufacturer=Yageo, Power_W=100mW, Supplier Part Number 1=311-5.1KGRCT-ND, TempCo="100 ppm/C", Tolerance_%=5%, Value2=0.1W, Value_Code=5k10, ValueDisplayed=5.1k
R18 R20 R27 R28 R29 R33 R44 R45 R47 R49 R50 R52 R55 R56 R59 R60 R64 R66 R70 R75 R78 R96 R98 R172 R173 R174 R175 R176 R177 R178 R179 R180 R181 R182 R183 R184 R185 R186 R187 R188 R189 R190 R191 R192 R193 R194 R195 R196 R197 R198 R212: library part CMP-0025874-4, "RES, 0, 5%, 0.1 W, AEC-Q200 Grade 0, 0603", Manufacturer=Panasonic, Power_W=100mW, Supplier Part Number 1=P0.0GCT-ND, TempCo="600 ppm/C", Tolerance_%=5%, Value2=0.1W, Value_Code=0000, ValueDisplayed=0
R19: library part CMP-0025769-4, "RES, 2.2 k, 5%, 0.1 W, AEC-Q200 Grade 0, 0603", Manufacturer=Vishay-Dale, Power_W=100mW, Supplier Part Number 1=541-2.2KGCT-ND, TempCo="200 ppm/C", Tolerance_%=5%, Value2=0.1W, Value_Code=2k20, ValueDisplayed=2.2k
R21 R57: library part CMP-0022895-5, "RES, 1.00 k, 1%, 0.1 W, 0603", Manufacturer=Yageo, Power_W=100mW, Supplier Part Number 1=311-1.00KHRCT-ND, TempCo="100 ppm/C", Tolerance_%=1%, Value2=0.1W, Value_Code=1k00, ValueDisplayed=1.00k
R22 R23: library part CMP-0025701-4, "RES, 10 k, 5%, 0.1 W, AEC-Q200 Grade 0, 0603", Manufacturer=Vishay-Dale, Power_W=100mW, Supplier Part Number 1=541-10KGCT-ND, TempCo="200 ppm/C", Tolerance_%=5%, Value2=0.1W, Value_Code=10k0, ValueDisplayed=10k
R24: library part CMP-0025927-5, "RES, 4.7 k, 5%, 0.1 W, 0603", Manufacturer=Yageo, Power_W=100mW, Supplier Part Number 1=311-4.7KGRCT-ND, TempCo="100 ppm/C", Tolerance_%=5%, Value2=0.1W, Value_Code=4k70, ValueDisplayed=4.7k
R25: library part CMP-0023109-5, "RES, 430, 1%, 0.1 W, 0603", Manufacturer=Yageo, Power_W=100mW, Supplier Part Number 1=311-430HRCT-ND, TempCo="100 ppm/C", Tolerance_%=1%, Value2=0.1W, Value_Code=430R, ValueDisplayed=430
R26: library part CMP-0025894-5, "RES, 1.2 k, 5%, 0.1 W, 0603", Manufacturer=Yageo, Power_W=100mW, Supplier Part Number 1=311-1.2KGRCT-ND, TempCo="100 ppm/C", Tolerance_%=5%, Value2=0.1W, Value_Code=1k20, ValueDisplayed=1.2k
R30: library part CMP-0026586-2, "RES, 88.7 k, 1%, 0.063 W, AEC-Q200 Grade 0, 0402", Manufacturer=Vishay-Dale, Power_W=63mW, Supplier Part Number 1=541-88.7KLCT-ND, TempCo="100 ppm/C", Tolerance_%=1%, Value2=0.063W, Value_Code=88k7, ValueDisplayed=88.7k
R32 R105 R106 R108 R141 R142 R204 R205: library part CMP-0026631-1, "RES, 4.70 k, 1%, 0.063 W, 0402", Manufacturer="TE Connectivity", Power_W=63mW, Supplier Part Number 1=A121542CT-ND, TempCo="100 ppm/C", Tolerance_%=1%, Value2=0.063W, Value_Code=4k70, ValueDisplayed=4.70k
R39 R40 R139 R140: library part CMP-0026863-2, "RES, 1.5 M, 5%, 0.063 W, AEC-Q200 Grade 0, 0402", Manufacturer=Vishay-Dale, Power_W=63mW, Supplier Part Number 1=541-1.5MJCT-ND, TempCo="200 ppm/C", Tolerance_%=5%, Value2=0.063W, Value_Code=1M50, ValueDisplayed=1.5M
R41: library part CMP-0026815-1, "RES, 100 k, 0.1%, 0.063 W, 0402", Manufacturer="Susumu Co Ltd", Power_W=63mW, Supplier Part Number 1=RG10P100KBCT-ND, TempCo="25 ppm/C", Tolerance_%=0.1%, Value2=0.063W, Value_Code=100k
R42 R61: library part CMP-0026918-5, "RES, 3.3 k, 5%, 0.063 W, AEC-Q200 Grade 0, 0402", Manufacturer=Vishay-Dale, Power_W=63mW, Supplier Part Number 1=541-3.3KJCT-ND, TempCo="200 ppm/C", Tolerance_%=5%, Value2=0.063W, Value_Code=3k30, ValueDisplayed=3.3k
R48 R69 R71 R74 R76: library part CMP-0081856-1, "RES, 0, 0%, 0.2 W, AEC-Q200 Grade 0, 0402", Manufacturer=Vishay-Dale, Power_W=200mW, Supplier Part Number 1=541-0.0YBTR-ND, Tolerance_%=0%, Value2=0.2W, Value_Code=0
R53 R90 R104: library part CMP-0025698-4, "RES, 100 k, 5%, 0.1 W, AEC-Q200 Grade 0, 0603", Manufacturer=Vishay-Dale, Power_W=100mW, Supplier Part Number 1=541-100KGCT-ND, TempCo="200 ppm/C", Tolerance_%=5%, Value2=0.1W, Value_Code=100k
R62 R63: library part CMP-0026949-3, "RES, 56 k, 5%, 0.063 W, AEC-Q200 Grade 0, 0402", Manufacturer=Vishay-Dale, Power_W=63mW, Supplier Part Number 1=541-56KJCT-ND, TempCo="200 ppm/C", Tolerance_%=5%, Value2=0.063W, Value_Code=56k0, ValueDisplayed=56k
R65 R67 R68: library part CMP-0026765-1, "RES, 10.0, 0.1%, 0.063 W, 0402", Manufacturer="TE Connectivity", Power_W=63mW, Supplier Part Number 1=A102583CT-ND, TempCo="25 ppm/C", Tolerance_%=0.1%, Value2=0.063W, Value_Code=10R0, ValueDisplayed=10.0
R85: library part CMP-0020620-3, "RES, 10 k, 5%, 0.125 W, AEC-Q200 Grade 0, 0805", Manufacturer=Panasonic, Power_W=125mW, Supplier Part Number 1=P10KACT-ND, TempCo="200 ppm/C", Tolerance_%=5%, Value2=0.125W, Value_Code=10k0, ValueDisplayed=10k
R88 R89 R111 R112 R113 R127 R128 R129 R130 R133 R145 R146 R147 R161 R162 R163: library part CMP-0026237-2, "RES, 2.49 k, 1%, 0.063 W, AEC-Q200 Grade 0, 0402", Manufacturer=Vishay-Dale, Power_W=63mW, Supplier Part Number 1=541-2.49KLCT-ND, TempCo="100 ppm/C", Tolerance_%=1%, Value2=0.063W, Value_Code=2k49, ValueDisplayed=2.49k
R95: library part CMP-0026068-3, "RES, 19.6 k, 1%, 0.063 W, AEC-Q200 Grade 0, 0402", Manufacturer=Vishay-Dale, Power_W=63mW, Supplier Part Number 1=541-19.6KLCT-ND, TempCo="100 ppm/C", Tolerance_%=1%, Value2=0.063W, Value_Code=19k6, ValueDisplayed=19.6k
R102 R206: library part CMP-0026963-3, "RES, 68 k, 5%, 0.063 W, AEC-Q200 Grade 0, 0402", Manufacturer=Vishay-Dale, Power_W=63mW, Supplier Part Number 1=541-68KJCT-ND, TempCo="200 ppm/C", Tolerance_%=5%, Value2=0.063W, Value_Code=68k0, ValueDisplayed=68k
R107 R123 R124 R125 R151 R159 R160 R202: library part CMP-0026231-2, "RES, 2.20 k, 1%, 0.063 W, AEC-Q200 Grade 0, 0402", Manufacturer=Vishay-Dale, Power_W=63mW, Supplier Part Number 1=541-2.20KLCT-ND, TempCo="100 ppm/C", Tolerance_%=1%, Value2=0.063W, Value_Code=2k20, ValueDisplayed=2.20k
R109 R143: library part CMP-0026515-2, "RES, 6.49 k, 1%, 0.063 W, AEC-Q200 Grade 0, 0402", Manufacturer=Vishay-Dale, Power_W=63mW, Supplier Part Number 1=541-6.49KLCT-ND, TempCo="100 ppm/C", Tolerance_%=1%, Value2=0.063W, Value_Code=6k49, ValueDisplayed=6.49k
R114 R115 R116 R117 R118 R119 R120 R121 R122 R126 R148 R149 R150 R152 R153 R154 R155 R156 R157 R158: library part CMP-0026299-2, "RES, 33.2, 1%, 0.063 W, AEC-Q200 Grade 0, 0402", Manufacturer=Vishay-Dale, Power_W=63mW, Supplier Part Number 1=541-33.2LCT-ND, TempCo="100 ppm/C", Tolerance_%=1%, Value2=0.063W, Value_Code=33R2, ValueDisplayed=33.2
R131 R134 R166 R168: library part CMP-0086542-2, "RMCF/RMCP Series General Purpose Thick Film Standard Power and High Power Chip Resistor", Manufacturer=Stackpole, TempCo=-
R132 R135 R167 R169: library part CMP-0025813-4, "RES, 470, 5%, 0.1 W, AEC-Q200 Grade 0, 0603", Manufacturer=Vishay-Dale, Power_W=100mW, Supplier Part Number 1=541-470GCT-ND, TempCo="200 ppm/C", Tolerance_%=5%, Value2=0.1W, Value_Code=470R, ValueDisplayed=470
R137: library part CMP-0026081-3, "RES, 1.27 k, 1%, 0.063 W, AEC-Q200 Grade 0, 0402", Manufacturer=Vishay-Dale, Power_W=63mW, Supplier Part Number 1=541-1.27KLCT-ND, TempCo="100 ppm/C", Tolerance_%=1%, Value2=0.063W, Value_Code=1k27, ValueDisplayed=1.27k
R171: library part CMP-0026027-3, "RES, 15.0 k, 1%, 0.063 W, AEC-Q200 Grade 0, 0402", Manufacturer=Vishay-Dale, Power_W=63mW, Supplier Part Number 1=541-15.0KLCT-ND, TempCo="100 ppm/C", Tolerance_%=1%, Value2=0.063W, Value_Code=15k0, ValueDisplayed=15.0k
R199 R200 R201: library part CMP-0078660-1, "RES, 0.1, 1%, 0.25 W, 0402", Manufacturer=Panasonic, Power_W=250mW, Supplier Part Number 1=P17368CT-ND, TempCo="300 ppm/C", Tolerance_%=1%, Value2=0.25W, Value_Code=R100, ValueDisplayed=0.1
S1: library part CMP-0002230-1, "Switch, SPST, 2 Pos, 25mA, 24VDC, SMD", CurrentRating_mA=25A, Manufacturer="CTS Electrocomponents", Supplier Part Number 1=CT2182LPST-ND
S2 S3 S5 S6: library part CMP-0002233-1, "Switch, Dual SPDT,  2 Pos, 0.1A, 6VDC, SMD", CurrentRating_mA=100A, Manufacturer="Copal Electronics", Supplier Part Number 1=CASD20JCT-ND
S4: library part CMP-0002328-1, "Switch, SPST, 0.05 A, 12 VDC, SMD", CurrentRating_mA=50A, Manufacturer=Diptronics
T1: library part CMP-0030623-1, "Transformer, 105uH, TH", Manufacturer="Wurth Elektronik", ValueDisplayed=105uH
TP1 TP2 TP3 TP4 TP5 TP6 TP7 TP8 TP9 TP10 TP11: library part CMP-0078143-3, "TEST POINT.  No entry in BOM.", Manufacturer=N/A
U1: library part CMP-0096042-2, "Real-Time Microcontroller NFBGA256", Frequency_Fixed=200MHz, Manufacturer="Texas Instruments", Operating Temperature Range=to
U2: library part CMP-0077953-1, "MSP432E401YTPDT, PDT0128A (TQFP-128)", Alternate Manufacturer="Texas Instruments", Alternate PartNumber=MSP432E401YTPDTR
U3: library part CMP-0076095-1, "Low-Noise 1 A, 420 kHz Transformer Driver, DBV0006A (SOT-23-6)", Alternate Manufacturer="Texas Instruments", Alternate PartNumber=SN6505BDBVT
U4 U13 U17 U19: library part CMP-0073613-3, "4-Channel Ultra-Low-Capacitance IEC ESD Protection Diode, DQA0010A (USON-10)", Alternate Manufacturer="Texas Instruments"
U5: library part CMP-0043361-3, "Dual In / Single Out Autoswitching Power Mux, 2.8 to 5.5 V, -40 to 85 degC, 9-pin SON (DRB), Green (RoHS & no Sb/Br)", IN1 Output Current(Max)(A)=1.25, IN1, IN2 Input Voltage(Max)(V)=5.5, IN1, IN2 Input Voltage(Min)(V)=2.8, Manufacturer="Texas Instruments"
U6: library part CMP-0067607-3, "High Speed, Robust EMC, Reinforced Six-Channel Digital Isolator, DBQ0016A (SSOP-16)", Alternate Manufacturer="Texas Instruments", Alternate PartNumber=ISO7762DBQ
U7: library part CMP-0091594-1, "IC SW BUS 8B FET LV 20-TSSOP,3.3-V, 1:1 (SPST), 8-channel FET high bandwidth bus switch with 2 control inputs", Digikey Part Number=296-17824-1-ND, Manufacturer="Texas Instruments", Max Supply Voltage=3.6V, Min Supply Voltage=2.3V, Mouser Part Number=595-SN74CB3Q3244PWR, Nominal Supply Current=0.7mA, Operating Temperature Range="-40°C to +85°C"
U8: library part CMP-0091939-1, "Linear Voltage Regulator IC Positive Fixed 1 Output 300mA SOT-23-5", Digikey Part Number=296-47851-1-ND, Dropout Voltage=260mV, Manufacturer="Texas Instruments", Max Supply Voltage=5.5V, Min Supply Voltage=2V, Mouser Part Number=595-TLV70333DBVR, Nominal Supply Current=35-370uA, Operating Temperature Range="-40°C to +125°C", Output Voltage=3.3V
U9 U20 U21 U22: library part CMP-0073614-1, "6-Channel Ultra-Low-Capacitance IEC ESD Protection Diodes, RVZ0014A (USON-14)", Alternate Manufacturer="Texas Instruments"
U10: library part CMP-0051789-2, "Dual Buffer/Driver with Open-Drain Output, DBV0006A, LARGE T&R", F @ Nom Voltage(Max)(Mhz)=150, Generic Part Number=SN74LVC2G07, ICC @ Nom Voltage(Max)(mA)=0.01, Manufacturer="Texas Instruments", Operating Temperature Range(C)="-40 to 125", Rating=Catalog, tpd @ Nom Voltage(Max)(ns)=8.6,4.4,3.7,2.9, Voltage(Nom)(V)=1.8,2.5,3.3,5
U11: library part CMP-0750051-1, "Overvoltage and Undervoltage Reset IC With Time Delay and Manual Reset, DSE0006A (WSON-6)", Alternate Manufacturer="Texas Instruments"
U12: library part CMP-0081428-2, "Automotive Precision Voltage Supervisor With Programmable Window Watchdog Timer, DRC0010R (VSON-10)", Alternate Manufacturer="Texas Instruments", Operating Temperature Range="-40 to 125 C", Rating=Automotive
U14: library part CMP-0074276-1, "Single, Current-Limited, Power-Distribution Switch, DBV0005A (SOT-23-5)", Alternate Manufacturer="Texas Instruments", Alternate PartNumber=TPS2051BDBVT
U15: library part CMP-0094192-1, "2.7-V to 6-V Adjustable-Frequency Dual Step-Down Converter in QFN package", Manufacturer="Texas Instruments", Max Supply Voltage=6V, Min Supply Voltage=2.7V, Nominal Supply Current=22-33uA, Operating Temperature Range="-40°C to +150°C", Output Voltage=0.6-5.5V, Switching Frequency=1.8-4MHz
U16: library part CMP-0082059-1, "16 Kb I2C EEPROM Serial, SOIC-8", Manufacturer="ON Semiconductor", Supplier Part Number 1=CAT24C16WI-GT3CT-ND
U18: library part CMP-0051777-2, "Dual Inverter Buffer/Driver with Open-Drain Output, DBV0006A, LARGE T&R", F @ Nom Voltage(Max)(Mhz)=150, Generic Part Number=SN74LVC2G06, ICC @ Nom Voltage(Max)(mA)=0.01, Manufacturer="Texas Instruments", Operating Temperature Range(C)="-40 to 125,-40 to 85", Rating=Catalog, tpd @ Nom Voltage(Max)(ns)=8.2,4.4,3.9,3.4, Voltage(Nom)(V)=1.8,2.5,3.3,5
U23: library part CMP-0032592-1, "Low Noise, Very Low Drift, Precision Voltage Reference, -40 to 125 degC, 8-pin SOIC (D), Green (RoHS & no Sb/Br)", Manufacturer="Texas Instruments", Rating=Catalog, Temp Coeff(Max)(ppm/ degree C)=3
U24: library part CMP-0041147-1, "High-Speed, Single-Supply, Rail-to-Rail Operational Amplifier MicroAmplifier(TM) Series, 2.7 to 5.5 V, -55 to 150 degC, 16-pin SOP (DBQ16), Green (RoHS & no Sb/Br)", Manufacturer="Texas Instruments", Total Supply Voltage(Max)(+5V is 5, +/-5V is 10)=5.5, Total Supply Voltage(Min)(+5V is 5, +/-5V is 10)=2.7
U25 U26: library part CMP-0001411-1, "Ethernet PHY 10BASE-Te/00BASE-TX 10/100 Mbps 160mW 1.8V/3.3V 2-Pin VQFN Industrial", Digikey Part Number=296-DP83826IRHBRCT-ND, Manufacturer="Texas Instruments", Max Supply Voltage=3.6V, Min Supply Voltage=1.62V, Mouser Part Number=595-DP83826IRHBR, Operating Temperature Range="-40°C to +85°C"
Y1: library part CMP-0094478-1, "Crystal 16 MHz ±20ppm Crystal 8pF 70 Ohms 4-SMD, No Lead", Digikey Part Number=732-830064296CT-ND, Frequency Stability=20ppm, Frequency_Fixed=16MHz, Load Capacitance=8pF, Manufacturer=Wurth, Mouser Part Number=710-830064296, Operating Temperature Range="-10°C to +70°C"
Y2: library part CMP-0096024-2, "High-Performance BAW Oscillator", Frequency Stability=25ppm, Frequency_Fixed=25MHz, Load Capacitance=30pF, Manufacturer="Texas Instruments", Max Supply Current=50mA, Max Supply Voltage=3.465V, Min Supply Voltage=2.375V, Operating Temperature Range="-40°C to +105°C"
Y3: library part CMP-0096023-2, "High-Performance BAW Oscillator 20MHz 2.5V-3.3V ±5% VSON4", Frequency Stability=25ppm, Frequency_Fixed=20MHz, Load Capacitance=30pF, Manufacturer="Texas Instruments", Max Supply Current=50mA, Max Supply Voltage=3.465V, Min Supply Voltage=2.375V, Operating Temperature Range="-40°C to +105°C"
ZZ1: library part CMP-0003616-3
ZZ2: library part CMP-0077236-1
ZZ3: library part CMP-0077237-1
ZZ4: library part CMP-0077238-1

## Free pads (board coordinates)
  round 1.778 hole 1.143: 6(147.087,36.176) 6(147.087,83.116)

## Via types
v1: diameter 0.559, hole 0.203, Top Layer to Bottom, tented both sides, 810 vias
v2: diameter 0.457, hole 0.203, Top Layer to Bottom, tented both sides, 153 vias
v3: diameter 0.5, hole 0.2, Top Layer to Bottom, tented both sides, 10 vias
v4: diameter 0.5, hole 0.2, Top Layer to Bottom, tented bottom, 4 vias
v5: diameter 0.5, hole 0.2, Top Layer to Bottom, tented top, 4 vias

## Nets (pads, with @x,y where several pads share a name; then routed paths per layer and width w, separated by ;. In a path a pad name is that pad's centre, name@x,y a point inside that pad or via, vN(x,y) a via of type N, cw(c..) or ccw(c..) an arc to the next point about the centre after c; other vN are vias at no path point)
1V2: C84.2 EC1.118 L5.1 R101.2 | length 59
  Top Layer w0.508: v1(100.863,31.852) 100.863,32.385 104.851,36.373 104.851,39.37 105.461,39.98 127.229,39.98 v1(127.889,40.64)
  Bottom w0.305: v1(105.614,61.061) 106.923,59.753 C84.2@106.923,59.512 ; L5.1@108.709,57.244 108.788,57.164 v1(108.788,54.331)
  Bottom w0.508: v1(100.863,31.852) 100.863,31.838 101.557,31.144 EC1.118@101.557,28.836 ; v1(127.889,42.52) 125.951,44.458 125.951,51.412 126.55,52.011 R101.2@128.96,52.011 128.952,52.019 128.952,56.242 v1(128.418,56.776)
